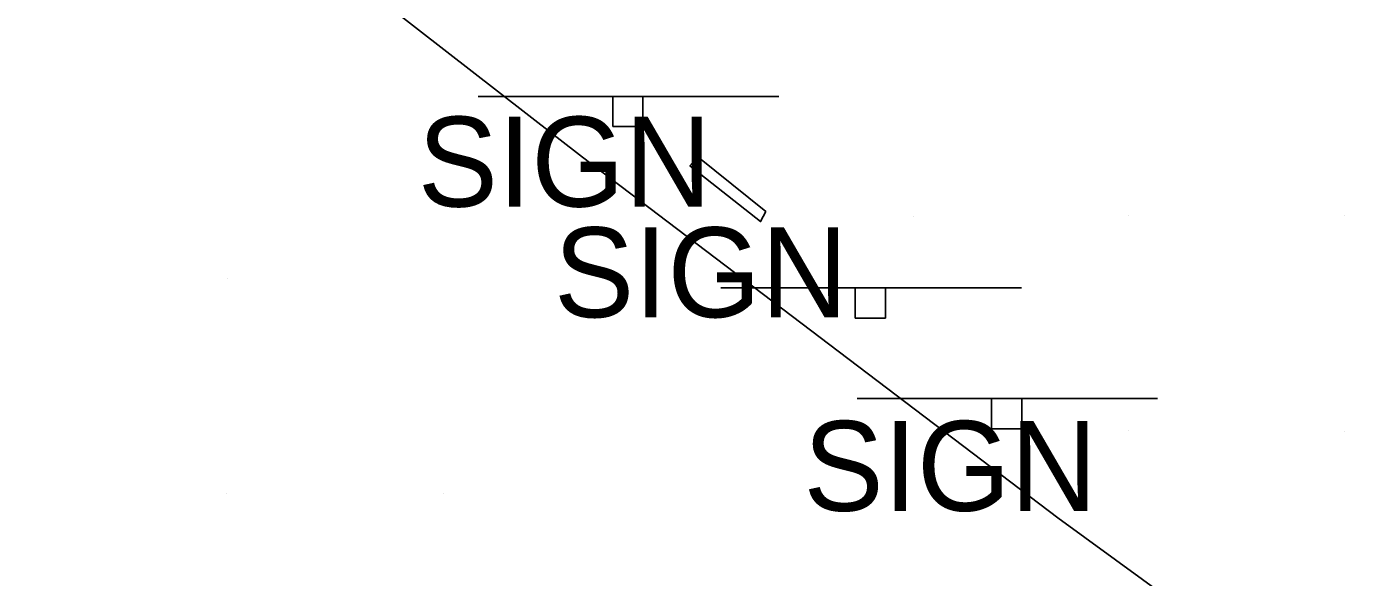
# Model space of a CAD drawing. Extents: x 1602514 to 1609837, y 863887 to 871157.
# Drawn here: x 1604716.3 to 1604808.5, y 866835.7 to 866874 of the extents above; entities that cross this region are included whole.
import ezdxf

# ---------------------------------------------------------------- set-up
doc = ezdxf.new("R2010")
doc.units = 0
for name, color, linetype in [('Roadway-Signs', 7, 'Continuous'), ('Survey-Edge of pavement', 7, 'Continuous'), ('Survey-Signs', 7, 'Continuous'), ('Survey-Spot dirt', 7, 'Continuous')]:
    doc.layers.add(name, color=color, linetype=linetype)

msp = doc.modelspace()

# ---------------------------------------------------------------- linework, layer by layer
at = {"layer": 'Roadway-Signs'}
for p, q in [((1604747.681, 866869.107), (1604768.583, 866869.107)), ((1604747.681, 866869.107), (1604768.583, 866869.107)), ((1604757.032, 866867.007), (1604757.032, 866869.107)), ((1604757.032, 866867.007), (1604757.032, 866869.107)), ((1604758.082, 866869.107), (1604758.082, 866869.107)), ((1604758.082, 866869.107), (1604758.082, 866869.107)), ((1604759.132, 866869.107), (1604759.132, 866867.007)), ((1604759.132, 866869.107), (1604759.132, 866867.007)), ((1604759.132, 866867.007), (1604757.032, 866867.007)), ((1604759.132, 866867.007), (1604757.032, 866867.007)), ((1604764.548, 866855.789), (1604785.449, 866855.789)), ((1604764.548, 866855.789), (1604785.449, 866855.789)), ((1604773.898, 866853.689), (1604773.898, 866855.789)), ((1604773.898, 866853.689), (1604773.898, 866855.789)), ((1604774.948, 866855.789), (1604774.948, 866855.789)), ((1604774.948, 866855.789), (1604774.948, 866855.789)), ((1604775.998, 866855.789), (1604775.998, 866853.689)), ((1604775.998, 866855.789), (1604775.998, 866853.689)), ((1604775.998, 866853.689), (1604773.898, 866853.689)), ((1604775.998, 866853.689), (1604773.898, 866853.689)), ((1604774.02, 866848.095), (1604794.921, 866848.095)), ((1604774.02, 866848.095), (1604794.921, 866848.095)), ((1604783.37, 866845.995), (1604783.37, 866848.095)), ((1604783.37, 866845.995), (1604783.37, 866848.095)), ((1604784.42, 866848.095), (1604784.42, 866848.095)), ((1604784.42, 866848.095), (1604784.42, 866848.095)), ((1604785.47, 866848.095), (1604785.47, 866845.995)), ((1604785.47, 866848.095), (1604785.47, 866845.995)), ((1604785.47, 866845.995), (1604783.37, 866845.995)), ((1604785.47, 866845.995), (1604783.37, 866845.995))]:
    msp.add_line(p, q, dxfattribs=at)
at = {"layer": 'Survey-Edge of pavement'}
msp.add_lwpolyline([(1604691.745, 866913.926), (1604754.929, 866864.888), (1604787.982, 866839.792), (1604824.932, 866812.891)], dxfattribs=at)
msp.add_lwpolyline([(1604691.745, 866913.926), (1604754.929, 866864.888), (1604787.982, 866839.792), (1604824.932, 866812.891)], dxfattribs=at)
at = {"layer": 'Survey-Signs'}
msp.add_lwpolyline([(1604762.939, 866864.903), (1604767.676, 866861.099), (1604767.312, 866860.408), (1604762.402, 866864.291)], close=True, dxfattribs=at)
msp.add_lwpolyline([(1604762.939, 866864.903), (1604767.676, 866861.099), (1604767.312, 866860.408), (1604762.402, 866864.291)], close=True, dxfattribs=at)
at = {"layer": 'Survey-Spot dirt'}
for p, q in [((1604777.941, 866860.764), (1604777.941, 866860.764)), ((1604777.941, 866860.764), (1604777.941, 866860.764)), ((1604792.884, 866860.807), (1604792.884, 866860.807)), ((1604792.884, 866860.807), (1604792.884, 866860.807)), ((1604807.928, 866860.847), (1604807.928, 866860.847)), ((1604807.928, 866860.847), (1604807.928, 866860.847)), ((1604730.225, 866856.417), (1604730.225, 866856.417)), ((1604730.225, 866856.417), (1604730.225, 866856.417)), ((1604792.927, 866845.876), (1604792.927, 866845.876)), ((1604792.927, 866845.876), (1604792.927, 866845.876)), ((1604807.893, 866845.819), (1604807.893, 866845.819)), ((1604807.893, 866845.819), (1604807.893, 866845.819)), ((1604730.184, 866841.493), (1604730.184, 866841.493)), ((1604730.184, 866841.493), (1604730.184, 866841.493)), ((1604745.228, 866841.474), (1604745.228, 866841.474)), ((1604745.228, 866841.474), (1604745.228, 866841.474))]:
    msp.add_line(p, q, dxfattribs=at)

# ---------------------------------------------------------------- texts
at = {"layer": 'Roadway-Signs'}
for p in [(1604743.469, 866861.446), (1604743.469, 866861.446), (1604752.941, 866853.752), (1604752.941, 866853.752), (1604770.292, 866840.288), (1604770.292, 866840.288)]:
    msp.add_text('SIGN', height=6.2505, dxfattribs=at).set_placement(p)

doc.saveas('drawing.dxf')
